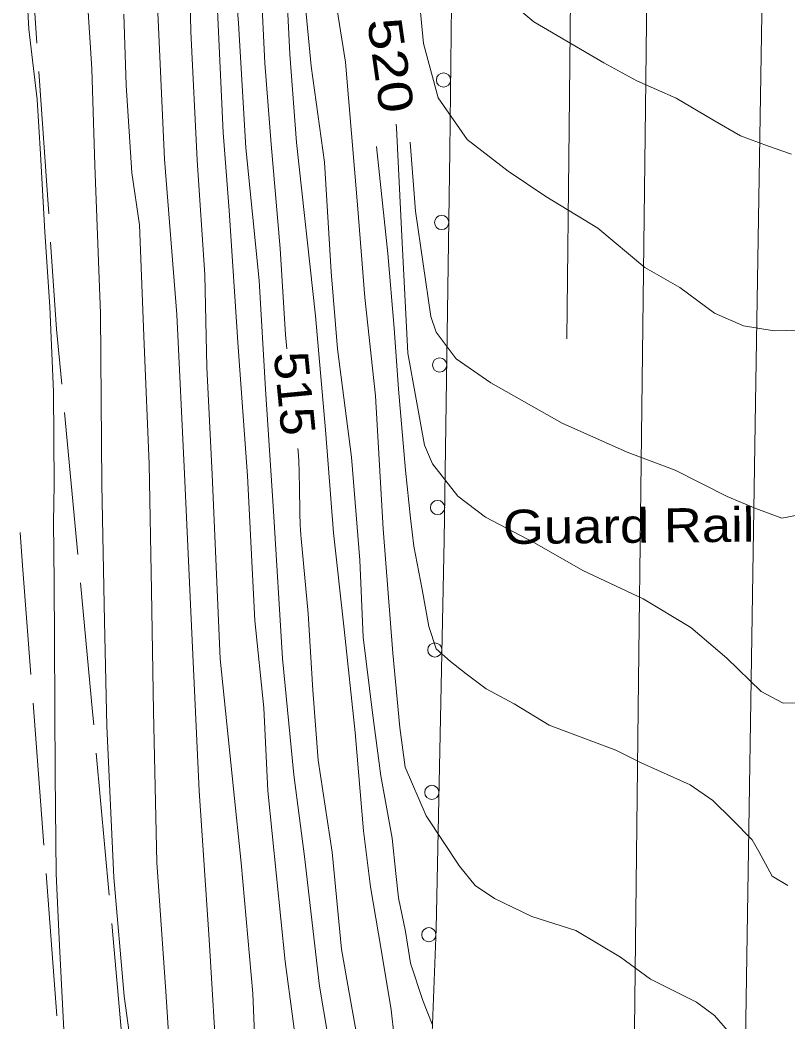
# Model space of a CAD drawing. Extents: x 2361284 to 2366480, y 6976556 to 6985346.
# Drawn here: x 2364367.1 to 2364474.8, y 6977781.3 to 6977922 of the extents above; entities that cross this region are included whole.
import ezdxf
from ezdxf.enums import TextEntityAlignment as Align

# ---------------------------------------------------------------- set-up
doc = ezdxf.new("R2010")
doc.units = 0
doc.header["$LTSCALE"] = 1.9
for name, color, linetype, lineweight in [('12', 7, 'Continuous', 13), ('13', 7, 'Continuous', 13), ('14', 7, 'Continuous', 13), ('15', 7, 'Continuous', 13), ('17', 7, 'Continuous', 13), ('3', 7, 'Continuous', 13)]:
    doc.layers.add(name, color=color, linetype=linetype, lineweight=lineweight)

msp = doc.modelspace()

# ---------------------------------------------------------------- linework, layer by layer
at = {"layer": '12'}
for points in [[(2364404.517, 6977875.829), (2364404.298, 6977877.777), (2364403.553, 6977889.88), (2364402.294, 6977904.519), (2364401.416, 6977915.88), (2364400.894, 6977926.597), (2364400.072, 6977942.6), (2364397.836, 6977971.6), (2364397.166, 6977990.525), (2364395.201, 6978010.988), (2364393.786, 6978024.104), (2364391.839, 6978046.957), (2364389.1, 6978070.002), (2364385.713, 6978100.102), (2364383.867, 6978120.786), (2364381.356, 6978138.682), (2364380.054, 6978151.581), (2364378.786, 6978162.948), (2364376.969, 6978178.383), (2364374.839, 6978196.253), (2364373.038, 6978213.178), (2364372.028, 6978220.518), (2364369.939, 6978234.07), (2364368.405, 6978247.155)], [(2364389.204, 6977763.646), (2364388.473, 6977771.06), (2364387.533, 6977785.632), (2364386.272, 6977803.71), (2364385.78, 6977824.907), (2364385.508, 6977841.916), (2364385.199, 6977859.694), (2364384.47, 6977876.399), (2364383.82, 6977893.232), (2364382.771, 6977900.533), (2364381.954, 6977912.805), (2364381.649, 6977922.794)], [(2364477.714, 6977826.121), (2364474.133, 6977826.087), (2364471.048, 6977827.698), (2364466.234, 6977832.383), (2364461.182, 6977836.715), (2364454.493, 6977840.722), (2364446.004, 6977844.711), (2364439.248, 6977848.577), (2364432.353, 6977852.192), (2364428.464, 6977855.145), (2364424.913, 6977859.666), (2364423.796, 6977862.301), (2364421.474, 6977875.189), (2364420.617, 6977891.612), (2364419.883, 6977906.817), (2364419.818, 6977907.326)], [(2364406.49, 6977849.186), (2364406.457, 6977849.653), (2364406.437, 6977849.964), (2364406.425, 6977850.171), (2364406.402, 6977850.586), (2364406.387, 6977850.898), (2364406.378, 6977851.106), (2364406.361, 6977851.521), (2364406.354, 6977851.729), (2364406.34, 6977852.145), (2364406.328, 6977852.56), (2364406.321, 6977852.838), (2364406.309, 6977853.392), (2364406.298, 6977854.016), (2364406.28, 6977855.265), (2364406.265, 6977856.375), (2364406.256, 6977856.93), (2364406.241, 6977857.762), (2364406.228, 6977858.317), (2364406.22, 6977858.594), (2364406.208, 6977859.01), (2364406.188, 6977859.564), (2364406.176, 6977859.841), (2364406.157, 6977860.256), (2364406.135, 6977860.671), (2364406.123, 6977860.879), (2364406.097, 6977861.294), (2364406.083, 6977861.501), (2364406.06, 6977861.812)], [(2364414.652, 6977777.619), (2364413.215, 6977785.706), (2364412.179, 6977791.547), (2364410.86, 6977805.174), (2364408.886, 6977818.067), (2364408.132, 6977827.909), (2364407.5, 6977838.685), (2364406.49, 6977849.186)]]:
    msp.add_lwpolyline(points, dxfattribs=at)
at = {"layer": '13'}
for points in [[(2364410.715, 6977886.608), (2364409.798, 6977902.011), (2364407.93, 6977915.492), (2364407.001, 6977924.855), (2364405.615, 6977945.443), (2364404.158, 6977966.16), (2364403.671, 6977979.456), (2364401.445, 6978001.186), (2364398.524, 6978028.579), (2364397.12, 6978047.908), (2364394.28, 6978074.192), (2364390.538, 6978108.048), (2364388.05, 6978130.856), (2364386.384, 6978151.611), (2364384.477, 6978163.924), (2364381.135, 6978193.533), (2364378.671, 6978217.031), (2364375.595, 6978239.764), (2364374.35, 6978252.902), (2364372.923, 6978263.079), (2364372.192, 6978270.633), (2364371.718, 6978276.228)], [(2364415.42, 6977883.002), (2364414.416, 6977896.043), (2364412.726, 6977916.028), (2364410.352, 6977931.077), (2364408.621, 6977946.931), (2364407.593, 6977966.682), (2364406.31, 6977983.831), (2364405.619, 6977990.266), (2364403.597, 6978008.307), (2364401.707, 6978031.43), (2364400.897, 6978038.773), (2364399.865, 6978051.613), (2364395.961, 6978083.538), (2364393.26, 6978106.824), (2364390.169, 6978131.116), (2364388.457, 6978150.281), (2364384.518, 6978178.535), (2364383.12, 6978196.162), (2364380.178, 6978222.645), (2364378.983, 6978237.876), (2364377.19, 6978254.009), (2364375.628, 6978264.745), (2364374.697, 6978276.407)], [(2364397.702, 6977921.506), (2364395.88, 6977943.78)], [(2364394.014, 6977858.187), (2364393.271, 6977873.241), (2364392.978, 6977886.189), (2364391.915, 6977902.27), (2364391.013, 6977920.343), (2364390.685, 6977934.85)], [(2364477.896, 6977878.467), (2364472.847, 6977878.349), (2364468.56, 6977879.038), (2364464.473, 6977880.839), (2364459.628, 6977884.442), (2364454.732, 6977887.216), (2364448.138, 6977892.754), (2364440.816, 6977897.174), (2364435.532, 6977900.735), (2364429.779, 6977905.171), (2364425.713, 6977911.041), (2364423.69, 6977918.682), (2364422.261, 6977933.35)], [(2364430.052, 6977679.811), (2364426.749, 6977683.22), (2364424.111, 6977686.154), (2364421.118, 6977693.776), (2364419.865, 6977700.485), (2364418.798, 6977706.525), (2364417.164, 6977713.299), (2364415.504, 6977719.524), (2364413.124, 6977729.052), (2364411.724, 6977740.52), (2364408.56, 6977759.84), (2364406.407, 6977773.74), (2364404.274, 6977789.832), (2364401.847, 6977813.77), (2364401.266, 6977825.404), (2364399.999, 6977837.673), (2364398.996, 6977857.985), (2364397.664, 6977876.034), (2364396.392, 6977895.242), (2364395.548, 6977906.155), (2364394.358, 6977932.485)], [(2364385.466, 6977677.037), (2364384.342, 6977685.826), (2364382.577, 6977694.789), (2364380.943, 6977705.765), (2364379.687, 6977716.893), (2364377.949, 6977733.438), (2364375.726, 6977747.478), (2364375.081, 6977756.342), (2364373.681, 6977771.089), (2364372.563, 6977793.001), (2364372.126, 6977802.116), (2364371.984, 6977816.036), (2364371.904, 6977834.926), (2364371.857, 6977842.996), (2364371.776, 6977851.526), (2364371.867, 6977856.707), (2364371.773, 6977869.797), (2364371.229, 6977881.722), (2364370.569, 6977892.226), (2364369.946, 6977903.122), (2364369.483, 6977910.807), (2364368.309, 6977920.677), (2364367.721, 6977930.902)], [(2364392.196, 6977813.758), (2364391.057, 6977837.908), (2364390.133, 6977858.281), (2364389.062, 6977880.611), (2364387.313, 6977902.417), (2364386.158, 6977928.157)], [(2364419.991, 6977775.55), (2364419.12, 6977783.022), (2364417.75, 6977791.53), (2364416.236, 6977800.325), (2364415.252, 6977808.146), (2364414.07, 6977821.947), (2364412.532, 6977836.473), (2364411.044, 6977849.969), (2364409.925, 6977864.429), (2364408.513, 6977880.457), (2364405.851, 6977904.783), (2364404.904, 6977917.174), (2364404.335, 6977928.55)], [(2364394.397, 6977671.731), (2364392.9, 6977689.217), (2364389.344, 6977710.965), (2364387.621, 6977723.86), (2364385.58, 6977747.021), (2364384.504, 6977764.542), (2364381.69, 6977784.946), (2364380.241, 6977801.633), (2364379.229, 6977822.855), (2364378.909, 6977837.603), (2364378.547, 6977856.78), (2364378.464, 6977868.64), (2364378.338, 6977880.789), (2364377.58, 6977901.594), (2364377.162, 6977915.12), (2364376.391, 6977926.814)], [(2364475.28, 6977903.153), (2364471.93, 6977904.301), (2364468.126, 6977905.725), (2364464.235, 6977907.948), (2364459.096, 6977910.989), (2364453.601, 6977913.447), (2364448.947, 6977915.932), (2364439.153, 6977921.721), (2364432.661, 6977927.189)], [(2364411.43, 6977772.538), (2364409.087, 6977786.387), (2364406.985, 6977804.547), (2364405.496, 6977816.005), (2364403.88, 6977832.35), (2364402.624, 6977853.008), (2364401.521, 6977870.129), (2364400.636, 6977885.392), (2364398.748, 6977904.026), (2364397.702, 6977921.506)], [(2364477.8, 6977852.814), (2364473.946, 6977852.047), (2364470.274, 6977853.402), (2364466.258, 6977855.104), (2364458.982, 6977858.795), (2364452.237, 6977861.331), (2364443.119, 6977865.385), (2364433.105, 6977871.03), (2364428.271, 6977874.424), (2364425.434, 6977878.146), (2364424.695, 6977880.341), (2364422.564, 6977895.111), (2364421.782, 6977904.795)], [(2364474.796, 6977800.482), (2364472.595, 6977801.781), (2364470.711, 6977805.283), (2364469.756, 6977806.904), (2364466.979, 6977809.769), (2364464.273, 6977812.423), (2364461.052, 6977814.613), (2364454.201, 6977817.718), (2364450.664, 6977819.484), (2364441.311, 6977823.016), (2364436.373, 6977825.998), (2364432.452, 6977828.111), (2364429.652, 6977830.204), (2364427.475, 6977831.924), (2364425.438, 6977833.715), (2364424.398, 6977836.835), (2364423.479, 6977842.047), (2364422.301, 6977848.126), (2364421.844, 6977852.052), (2364421.149, 6977858.795), (2364420.172, 6977870.137), (2364419.56, 6977878.722), (2364418.66, 6977889.213), (2364417.087, 6977904.23)], [(2364424.879, 6977781.026), (2364423.557, 6977784.354), (2364421.837, 6977789.589), (2364421.165, 6977794.033), (2364420.15, 6977798.762), (2364419.767, 6977802.199), (2364419.26, 6977807.134), (2364417.678, 6977815.891), (2364416.514, 6977824.72), (2364415.223, 6977835.358), (2364414.74, 6977846.174), (2364413.553, 6977860.603), (2364411.588, 6977875.796), (2364410.715, 6977886.608)], [(2364475.812, 6977775.64), (2364471.456, 6977776.369), (2364469.948, 6977777.225), (2364467.22, 6977779.109), (2364464.51, 6977782.253), (2364461.942, 6977784.139), (2364455.511, 6977787.349), (2364451.301, 6977790.439), (2364445.036, 6977794.17), (2364438.857, 6977796.161), (2364433.613, 6977798.65), (2364430.914, 6977800.505), (2364428.728, 6977803.224), (2364424.031, 6977810.281), (2364421.116, 6977817.113), (2364420.363, 6977822.666), (2364419.354, 6977833.097), (2364417.998, 6977850.555), (2364416.911, 6977869.236), (2364415.42, 6977883.002)], [(2364416.49, 6977675.811), (2364414.45, 6977691.622), (2364411.874, 6977702.669), (2364407.599, 6977715.778), (2364405.27, 6977730.338), (2364404.098, 6977738.987), (2364401.978, 6977753.657), (2364400.389, 6977769.333), (2364399.707, 6977785.337), (2364398.103, 6977803.653), (2364396.994, 6977814.054), (2364395.14, 6977832.307), (2364394.014, 6977858.187)], [(2364410.514, 6977668.024), (2364408.578, 6977680.077), (2364405.349, 6977693.586), (2364403.074, 6977702.576), (2364399.933, 6977720.537), (2364396.999, 6977742.99), (2364394.946, 6977760.191), (2364394.779, 6977773.56), (2364393.584, 6977792.93), (2364392.196, 6977813.758)]]:
    msp.add_lwpolyline(points, dxfattribs=at)
at = {"layer": '14'}
for points in [[(2364461.091, 6978393.234), (2364460.286, 6978354.391), (2364459.916, 6978334.969), (2364459.698, 6978322.02), (2364459.601, 6978315.546), (2364459.472, 6978305.834), (2364459.016, 6978266.021), (2364458.426, 6978212.938), (2364458.107, 6978186.396), (2364457.625, 6978149.176), (2364456.975, 6978099.55), (2364456.669, 6978074.736), (2364456.508, 6978060.846), (2364456.202, 6978033.066), (2364455.611, 6977977.505), (2364455.297, 6977949.725), (2364454.805, 6977909.571), (2364454.132, 6977856.033), (2364453.812, 6977829.264), (2364453.221, 6977776.246), (2364452.462, 6977705.555), (2364452.074, 6977670.209)], [(2364443.766, 6977877.192), (2364444.086, 6977906.797), (2364444.731, 6977966.006)]]:
    msp.add_lwpolyline(points, dxfattribs=at)
at = {"layer": '15'}
for p, q in [((2364368.068, 6977938.674), (2364369.437, 6977918.717)), ((2364369.715, 6977914.729), (2364371.085, 6977894.771)), ((2364373.301, 6977866.861), (2364375.17, 6977846.948)), ((2364370.408, 6977806.15), (2364368.888, 6977826.096)), ((2364377.765, 6977819.061), (2364379.565, 6977799.146)), ((2364372.235, 6977782.216), (2364370.716, 6977802.162)), ((2364379.923, 6977795.161), (2364381.732, 6977775.246))]:
    msp.add_line(p, q, dxfattribs=at)
for points in [[(2364371.363, 6977890.784), (2364372.199, 6977878.572), (2364372.923, 6977870.848)], [(2364368.59, 6977830.083), (2364367.424, 6977845.414), (2364367.07, 6977850.031)], [(2364375.548, 6977842.961), (2364377.24, 6977824.875), (2364377.407, 6977823.048)]]:
    msp.add_lwpolyline(points, dxfattribs=at)
at = {"layer": '17'}
msp.add_lwpolyline([(2364417.947, 6977503.656), (2364418.033, 6977518.786), (2364418.169, 6977533.909), (2364418.883, 6977585.019), (2364419.906, 6977636.132), (2364420.859, 6977672.722), (2364422.001, 6977709.306), (2364423.806, 6977751.845), (2364425.442, 6977794.393), (2364426.573, 6977848.967), (2364427.354, 6977903.548), (2364427.842, 6977944.754), (2364428.321, 6977985.96), (2364429.078, 6978056.702), (2364429.736, 6978127.442), (2364429.592, 6978174.103), (2364428.708, 6978220.757), (2364427.748, 6978255.45), (2364426.389, 6978290.129), (2364424.777, 6978320.776), (2364423.206, 6978351.412), (2364422.097, 6978377.613), (2364421.077, 6978403.814)], dxfattribs=at)
for centre in [(2364426.474, 6977913.537), (2364426.211, 6977893.541), (2364425.926, 6977873.543), (2364425.64, 6977853.545), (2364425.255, 6977833.555), (2364424.84, 6977813.559), (2364424.41, 6977793.582)]:
    msp.add_circle(centre, 1, dxfattribs=at)
at = {"layer": '3'}
msp.add_lwpolyline([(2364476.86, 6978388.164), (2364475.657, 6978327.472), (2364475.184, 6978297.124), (2364474.229, 6978216.704), (2364473.831, 6978176.494), (2364473.557, 6978129.148), (2364473.275, 6978066.02), (2364472.942, 6978034.458), (2364470.275, 6977871.183), (2364468.653, 6977766.677), (2364467.925, 6977714.422), (2364467.22, 6977644.472), (2364466.924, 6977597.838), (2364466.55, 6977504.568)], dxfattribs=at)

# ---------------------------------------------------------------- texts
at = {"layer": '12'}
for s, height, rotation, width, p in [(' 520 ', 4.8, 278.092, 1.25, (2364416.692, 6977915.272)), (' 515 ', 4.799, 275.545, 1.1, (2364403.215, 6977869.321))]:
    msp.add_text(s, height=height, rotation=rotation, dxfattribs=dict(at, width=width)).set_placement(p, align=Align.CENTER)
at = {"layer": '17', "width": 1.15}
msp.add_text('Guard Rail', height=4.799, rotation=0.545, dxfattribs=at).set_placement((2364434.84, 6977848.415))

doc.saveas('drawing.dxf')
